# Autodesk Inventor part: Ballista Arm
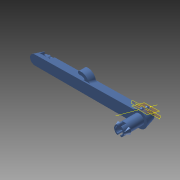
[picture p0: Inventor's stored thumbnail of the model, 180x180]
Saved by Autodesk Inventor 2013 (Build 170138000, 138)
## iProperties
Created: 2013-06
Part Number: Ballista Arm
Material: ABS Plastic
Document SubType Name: Modeling
Designer: merrill
Density: 1 g/cm^3
d0: 145.00 deg
d1: 2.000 in
d2: 0.200 in
d3: 15.00 deg
d4: 0.300 in
d5: 0.00 deg
d6: 0.100 in
d9: 0.200 in
d12: 0.075 in
d13: 0.025 in
d14: 0.100 in
d15: 0.00 deg
d18: 0.100 in
d20: 0.100 in
d21: 20.00 deg
d22: 0.075 in
d24: 0.100 in
d25: 0.200 in
d26: 0.250 in
d27: 0.100 in
d28: 0.00 deg
d31: 0.150 in
d33: 0.040 in
d34: 0.040 in
d35: 0.00 deg
d36: 0.010 in
d37: 0.010 in
d38: 0.160 in
d39: 0.040 in
d56: -0.100 in
d57: 0.00 deg
d58: 0.045 in
d67: 0.050 in
d68: 0.00 deg
d69: 0.040 in
d70: 0.030 in
d71: 0.050 in
d72: 0.020 in
d74: 90.00 deg
Author: merrill
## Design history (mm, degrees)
sketch "Sketch1"
  geometry: L1 (0, 0)-(-2.189, 1.533); L2 (0, 0)-(2.672, 0); L3 (-2.189, 1.533)-(-52.98, 0.587); L4 (-52.98, 0.587)-(-52.941, -1.533); L5 (-52.941, -1.533)-(-2.189, -1.533); A1 r 2.672 centre (0, 0) between (-2.189, 1.533) and (-2.189, -1.533); A2 r 2.672 centre (0, 0) between (-2.189, -1.533) and (-2.189, 1.533); A3 r 1.06 centre (-52.96, -0.473) between (-52.98, 0.587) and (-52.941, -1.533); 1 further point
  constraints: 10 end point, 6 point on circle, 3 centre point, 2 coincident, 1 concentric, 1 equal length, 1 horizontal, 1 parallel, 1 perpendicular, 1 tangent
  dimensions: "d0" = 145 deg angle of L2 L1; "d1" = 50.8 distance of L1.end L3.end
extrude "Extrusion1" new body sketch "Sketch1" distance "d2" = 5.08; taper "d3" = 15 deg
sketch "Sketch2"
  geometry: C1 r 2.54 at (0, 0); A1 r 4.033 centre (0, 0) between (-2.809, -2.894) and (-2.821, 2.882) reference
  constraints: 1 centre point, 1 coincident
  dimensions: "d9" = 5.08 diameter of C1
extrude "Extrusion2" join sketch "Sketch2" distance "d4" = 7.62; taper "d5" = 0 deg
sketch "Sketch3"
  geometry: L1 (0, 0)-(-1.202, 0); L2 (-1.202, 0)-(-1.202, 2.238); L3 (-1.202, 0)-(-1.202, -2.238); L4 (0, 4.288)-(0, -4.187) reference; L5 (-0.567, -1.858)-(-0.567, 1.911); L6 (1.202, 0)-(1.202, 2.238); L7 (1.202, 0)-(1.202, -2.238); L8 (0.567, -1.858)-(0.567, 1.911); A1 r 2.54 centre (0, 0) between (-1.202, 2.238) and (-1.202, -2.238); A2 r 1.905 centre (0, 0) between (-1.202, 1.478) and (-1.202, -1.478); A3 r 0.431 centre (-0.998, -1.858) between (-1.202, -2.238) and (-1.202, -1.478); A4 r 0.411 centre (-1.043, 1.858) between (-1.202, 1.478) and (-1.202, 2.238); A5 r 2.54 centre (0.001, 0) between (1.202, -2.238) and (1.202, 2.238); A6 r 1.905 centre (0.001, 0) between (1.202, -1.478) and (1.202, 1.478); A7 r 0.431 centre (0.998, -1.858) between (1.202, -1.478) and (1.202, -2.238); A8 r 0.411 centre (1.044, 1.858) between (1.202, 2.238) and (1.202, 1.478)
  constraints: 21 point on circle, 16 end point, 11 symmetric about line, 8 centre point, 4 point on line, 3 coincident, 2 parallel, 2 tangent, 1 collinear, 1 horizontal, 1 perpendicular, 1 vertical, 4 other
  dimensions: "d6" = 2.54 radius of A1; "d12" = 1.905 radius of A2; "d13" = 0.635 distance between parallel lines of L3 L5
extrude "Extrusion3" join sketch "Sketch3" distance "d14" = 2.54; taper "d15" = 0 deg
sketch "Sketch5"
  geometry: L1 (0, 2.95)-(0, -2.739) reference; L2 (0, 0)-(3.897, 0) reference; L3 (2.032, 0.508)-(2.032, -0.508); L4 (2.032, 0.508)-(2.489, 0.508); L5 (2.489, -0.508)-(2.032, -0.508); L6 (0, 0)-(-3.897, 0); L7 (-2.032, 0.508)-(-2.032, -0.508); L8 (-2.032, 0.508)-(-2.489, 0.508); L9 (-2.489, -0.508)-(-2.032, -0.508); A1 r 2.54 centre (0, 0) between (2.489, -0.508) and (2.489, 0.508); A2 r 2.54 centre (0, 0) between (-2.489, 0.508) and (-2.489, -0.508); 1 further point
  constraints: 18 end point, 5 symmetric about line, 4 point on circle, 3 coincident, 3 perpendicular, 2 centre point, 2 vertical, 1 horizontal, 1 parallel, 1 other
  dimensions: "d18" = 2.54 radius of A1; "d38" = 4.064 distance between parallel lines of L3 L7; "d39" = 1.016 distance between parallel lines of L5 L4
extrude "Extrusion4" join sketch "Sketch5" distance "d20" = 2.54; taper "d21" = 20 deg
sketch "Sketch6"
  geometry: L1 (47.88, 2.702)-(52.96, 2.702); L2 (52.96, 2.702)-(52.96, -3.648); L3 (52.96, -3.648)-(47.88, -3.648); L4 (47.88, -3.648)-(47.88, 2.702); L5 (50.42, 2.702)-(50.42, -3.648); L6 (47.88, -0.473)-(52.96, -0.473); L7 (52.96, -0.473)-(52.96, -0.473); C1 r 0.952 at (50.42, -0.473); A1 r 1.06 centre (52.96, -0.473) between (52.941, -1.533) and (52.98, 0.587) reference; 1 further point
  constraints: 14 end point, 5 midpoint, 2 parallel, 1 centre point, 1 coincident, 1 collinear, 1 horizontal, 1 perpendicular
  dimensions: "d22" = 1.905 diameter of C1; "d24" = 2.54 distance of L7.end C1.centre; "d25" = 5.08 distance of L1.start L1.end; "d26" = 6.35 distance of L1.end L2.end
extrude "Extrusion5" cut sketch "Sketch6" distance "d27" = 2.54; taper "d28" = 0 deg
sketch "Sketch10"
  geometry: L1 (1.905, -0.508)-(-1.905, -0.508); L2 (-1.905, -0.508)-(-1.905, 0.508); L3 (-1.905, 0.508)-(1.905, 0.508); L4 (1.905, 0.508)-(1.905, -0.508); L5 (-1.905, 0.508)-(1.905, -0.508); L6 (1.905, 0.508)-(-1.905, -0.508); C1 r 0.952 at (0, 0) reference; 2 further points
  constraints: 12 end point, 2 parallel, 1 coincident, 1 horizontal, 1 midpoint, 1 perpendicular
  dimensions: "d31" = 3.81 distance of L2.end L3.end; "d33" = 1.016 distance of L1.end L2.end
extrude "Extrusion7" join sketch "Sketch10" distance "d34" = 1.016; taper "d35" = 0 deg
fillet "Fillet1" dims "d36" = 0.254
fillet "Fillet2" dims "d37" = 0.254
workplane "Work Plane1"
sketch "Sketch16"
  geometry: L1 (27.094, 0)-(27.094, 1.232); A1 r 3.241 centre (30.336, 1.232) between (30.743, 4.447) and (27.094, 1.232); 1 further point
  constraints: 2 end point, 2 point on circle, 1 centre point, 1 tangent, 1 vertical
sketch "Sketch17"
  geometry: L1 (26.37, 4.176)-(28.025, 4.176); L2 (28.025, 4.176)-(28.025, 0.679); L3 (28.025, 0.679)-(26.37, 0.679); L4 (26.37, 0.679)-(26.37, 4.176); L5 (27.198, 4.176)-(27.198, 0.679); L6 (28.025, 2.428)-(26.37, 2.428); 2 further points
  constraints: 12 end point, 5 midpoint, 2 parallel, 1 horizontal, 1 perpendicular
sweep "Sweep2" sketch "Sketch16", "Sketch17" dims angle "d57" = 0 deg
sketch "Sketch21"
  geometry: L1 (0, 0)-(0, 1.655) reference; L2 (3.497, 0)-(0, 0) reference; L3 (3.497, 1.655)-(3.497, 0) reference; L4 (0, 1.655)-(3.497, 1.655) reference; 1 further point
extrude "Extrusion9" join sketch "Sketch21" distance "d67" = 1.27; taper "d68" = 0 deg
fillet "Fillet10" dims "d69" = 1.016
fillet "Fillet11" dims "d70" = 0.762
fillet "Fillet12" dims "d71" = 1.27
fillet "Fillet13" dims "d72" = 0.508
workplane "Work Plane2"
sketch "Sketch23"
  geometry: L1 (49.58, 2.392)-(57.228, 2.392); 1 further point
  constraints: 2 end point, 1 horizontal
workaxis "Work Axis3"
sketch "Sketch20"
  geometry: L1 (52.96, 5.666)-(52.96, 0.014)
  constraints: 2 end point, 1 vertical
workaxis "Work Axis1"
sketch "Sketch25"
  geometry: L1 (52.96, 2.717)-(52.96, 3.731) reference; L2 (52.195, 3.731)-(53.725, 3.731); A1 r 0.765 centre (52.96, 3.731) between (53.725, 3.731) and (52.195, 3.731); 1 further point
  constraints: 4 end point, 2 point on circle, 2 vertical, 1 centre point, 1 coincident, 1 perpendicular
revolve "Revolution2" sketch "Sketch25" stored, may be unused: angle "d73" = 225 deg
workplane "Work Plane3"
mirror "Mirror1"
body "Solid1"
other parameters: "d56" = -2.54, "d58" = 1.143, "d74" = 90 deg
